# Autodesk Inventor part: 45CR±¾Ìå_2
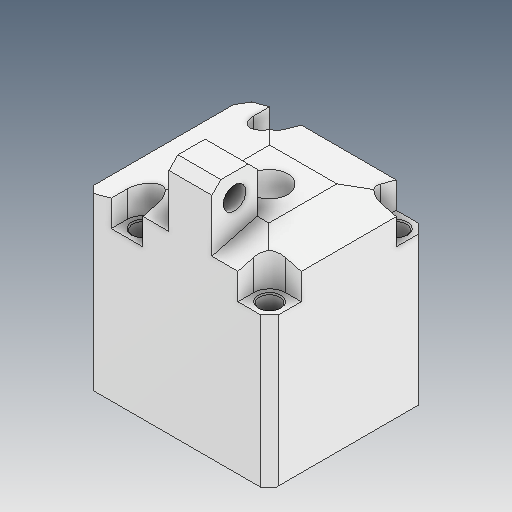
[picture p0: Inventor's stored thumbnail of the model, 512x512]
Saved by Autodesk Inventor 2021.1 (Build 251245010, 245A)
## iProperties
Created: 2021-05
Part Number: 45CR±¾Ìå_2
Material: Ogólny
Document SubType Name: Modeling
Designer: user
Density: 1 g/cm^3
Appearance: Domyślna
Author: user
Revision Number: ÈÎºÎ
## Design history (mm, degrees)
feature "ÊäÈë1"
node "Bryła1"
